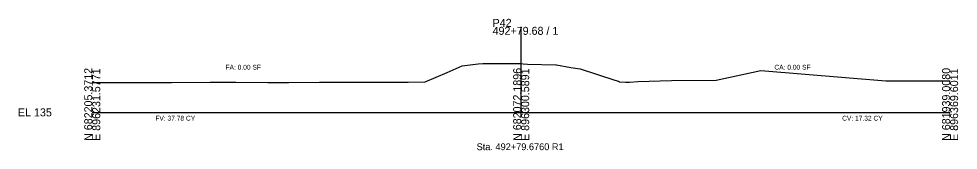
# Model space of a CAD drawing. Extents: x -100 to 7529, y -13 to 10775.
# Drawn here: x 3974.3 to 4302.8, y 1486.7 to 1532.8 of the extents above; entities that cross this region are included whole.
import ezdxf

# ---------------------------------------------------------------- set-up
doc = ezdxf.new("R2010")
doc.units = 0
for name, color, linetype in [('Draft_XS_Grid', 7, 'Continuous'), ('Draft_XS_Text', 7, 'Continuous'), ('DTM_X_GROUND', 7, 'Continuous'), ('XS_CELL', 7, 'Continuous'), ('XS_SHEET_EW_TX_AREA', 7, 'Continuous'), ('XS_SHEET_EW_TX_VOLUME', 7, 'Continuous')]:
    doc.layers.add(name, color=color, linetype=linetype)

msp = doc.modelspace()

# ---------------------------------------------------------------- linework, layer by layer
at = {"layer": 'DTM_X_GROUND'}
msp.add_lwpolyline([(4000, 1510.52), (4002.17, 1510.45), (4023.52, 1510.46), (4027.66, 1510.46), (4041.24, 1510.59), (4045.69, 1510.59), (4047.59, 1510.59), (4050.24, 1510.57), (4061.38, 1510.53), (4068.71, 1510.45), (4079.5, 1510.6), (4110.46, 1510.58), (4116.4, 1510.77), (4124.09, 1514), (4129.35, 1516.29), (4134.97, 1517.07), (4136.58, 1517.16), (4149.94, 1517.11), (4149.95, 1517.11), (4150.65, 1517.04), (4152.25, 1516.96), (4162.13, 1516.66), (4162.36, 1516.62), (4167.35, 1515.74), (4168.98, 1515.52), (4170.68, 1515.22), (4182.8, 1511.35), (4183.98, 1511), (4184.43, 1510.73), (4186.43, 1510.61), (4187.94, 1510.58), (4190.82, 1510.86), (4202.52, 1511.21), (4218.15, 1511.28), (4233.78, 1514.67), (4277.5, 1511.05), (4300, 1511.02)], dxfattribs=at)
at = {"layer": 'XS_CELL'}
for p, q in [((4150, 1500), (4150, 1530)), ((4150, 1500), (4150, 1530)), ((4000, 1500), (4150, 1500)), ((4000, 1500), (4150, 1500)), ((4150, 1500), (4300, 1500)), ((4150, 1500), (4300, 1500))]:
    msp.add_line(p, q, dxfattribs=at)

# ---------------------------------------------------------------- texts
at = {"layer": 'Draft_XS_Grid'}
msp.add_text('-', height=0.0001, dxfattribs=at).set_placement((4000, 1500))
at = {"layer": 'Draft_XS_Text'}
msp.add_text('Sta. 492+79.6760 R1', height=2.4, dxfattribs=at).set_placement((4134.42, 1486.75))
at = {"layer": 'XS_CELL'}
for s, p in [('P42', (4140, 1530)), ('P42', (4140, 1530)), ('492+79.68 / 1', (4140, 1527.2)), ('492+79.68 / 1', (4140, 1527.2)), ('EL 135', (3974, 1498.6)), ('EL 135', (3974, 1498.6))]:
    msp.add_text(s, height=2.8, dxfattribs=at).set_placement(p)
for s, p in [('N 682205.3712', (4000, 1490)), ('N 682205.3712', (4000, 1490)), ('E 896231.5771', (4002.8, 1490)), ('E 896231.5771', (4002.8, 1490)), ('N 682072.1896', (4150, 1490)), ('N 682072.1896', (4150, 1490)), ('E 896300.5891', (4152.8, 1490)), ('E 896300.5891', (4152.8, 1490)), ('N 681939.0080', (4300, 1490)), ('N 681939.0080', (4300, 1490)), ('E 896369.6011', (4302.8, 1490)), ('E 896369.6011', (4302.8, 1490))]:
    msp.add_text(s, height=2.8, rotation=90, dxfattribs=at).set_placement(p)
at = {"layer": 'XS_SHEET_EW_TX_AREA'}
for s, p in [('FA: 0.00 SF', (4046.6, 1515)), ('FA: 0.00 SF', (4046.6, 1515)), ('CA: 0.00 SF', (4238.56, 1515)), ('CA: 0.00 SF', (4238.56, 1515))]:
    msp.add_text(s, height=1.68, dxfattribs=at).set_placement(p)
at = {"layer": 'XS_SHEET_EW_TX_VOLUME'}
for s, p in [('FV: 37.78 CY', (4022.07, 1497.12)), ('FV: 37.78 CY', (4022.07, 1497.12)), ('CV: 17.32 CY', (4262.24, 1497.12)), ('CV: 17.32 CY', (4262.24, 1497.12))]:
    msp.add_text(s, height=1.68, dxfattribs=at).set_placement(p)

doc.saveas('drawing.dxf')
